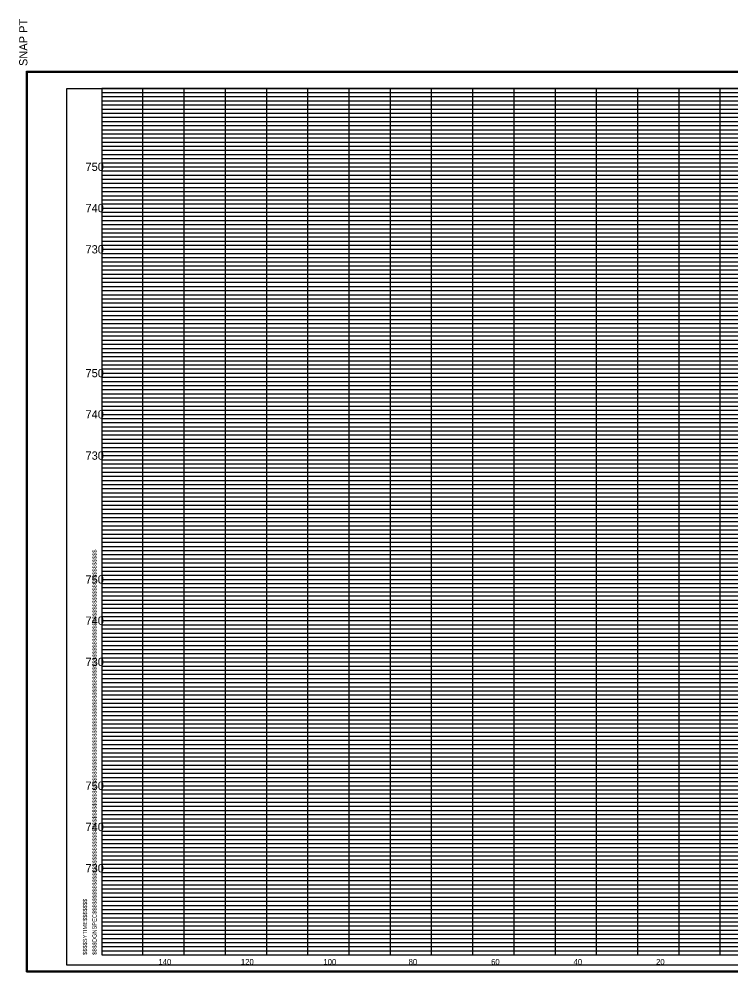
# Model space of a CAD drawing. Extents: x -200 to 1704, y -325 to 2307.
# Drawn here: x 1359.9 to 1532.6, y 995.9 to 1226.8 of the extents above; entities that cross this region are included whole.
import ezdxf

# ---------------------------------------------------------------- set-up
doc = ezdxf.new("R2010")
doc.units = 0
for name, color, linetype in [('DESIGN - SHEET - Corner Text', 7, 'Continuous'), ('DESIGN - SHEET - Light Grid', 7, 'Continuous'), ('DESIGN - SHEET - Linework', 7, 'Continuous'), ('DESIGN - SHEET - Plot Shape', 7, 'Continuous'), ('DESIGN - TYPICAL - Text', 7, 'Continuous')]:
    doc.layers.add(name, color=color, linetype=linetype)

msp = doc.modelspace()

# ---------------------------------------------------------------- linework, layer by layer
at = {"layer": 'DESIGN - SHEET - Light Grid'}
for p, q in [((1380, 1209), (1460, 1209)), ((1380, 1208), (1460, 1208)), ((1460, 1209), (1540, 1209)), ((1460, 1208), (1540, 1208)), ((1380, 1207), (1460, 1207)), ((1380, 1206), (1460, 1206)), ((1460, 1207), (1540, 1207)), ((1460, 1206), (1540, 1206)), ((1380, 1205), (1460, 1205)), ((1380, 1204), (1460, 1204)), ((1460, 1205), (1540, 1205)), ((1460, 1204), (1540, 1204)), ((1380, 1203), (1460, 1203)), ((1380, 1202), (1460, 1202)), ((1380, 1201), (1460, 1201)), ((1460, 1203), (1540, 1203)), ((1460, 1202), (1540, 1202)), ((1460, 1201), (1540, 1201)), ((1380, 1199), (1460, 1199)), ((1460, 1199), (1540, 1199)), ((1380, 1198), (1460, 1198)), ((1380, 1197), (1460, 1197)), ((1460, 1198), (1540, 1198)), ((1460, 1197), (1540, 1197)), ((1380, 1196), (1460, 1196)), ((1380, 1195), (1460, 1195)), ((1460, 1196), (1540, 1196)), ((1460, 1195), (1540, 1195)), ((1380, 1194), (1460, 1194)), ((1380, 1193), (1460, 1193)), ((1380, 1192), (1460, 1192)), ((1460, 1194), (1540, 1194)), ((1460, 1193), (1540, 1193)), ((1460, 1192), (1540, 1192)), ((1380, 1191), (1460, 1191)), ((1460, 1191), (1540, 1191)), ((1380, 1189), (1460, 1189)), ((1380, 1188), (1460, 1188)), ((1460, 1189), (1540, 1189)), ((1460, 1188), (1540, 1188)), ((1380, 1187), (1460, 1187)), ((1380, 1186), (1460, 1186)), ((1380, 1185), (1460, 1185)), ((1460, 1187), (1540, 1187)), ((1460, 1186), (1540, 1186)), ((1460, 1185), (1540, 1185)), ((1380, 1184), (1460, 1184)), ((1380, 1183), (1460, 1183)), ((1460, 1184), (1540, 1184)), ((1460, 1183), (1540, 1183)), ((1380, 1182), (1460, 1182)), ((1380, 1181), (1460, 1181)), ((1460, 1182), (1540, 1182)), ((1460, 1181), (1540, 1181)), ((1380, 1179), (1460, 1179)), ((1380, 1178), (1460, 1178)), ((1460, 1179), (1540, 1179)), ((1460, 1178), (1540, 1178)), ((1380, 1177), (1460, 1177)), ((1380, 1176), (1460, 1176)), ((1460, 1177), (1540, 1177)), ((1460, 1176), (1540, 1176)), ((1380, 1175), (1460, 1175)), ((1380, 1174), (1460, 1174)), ((1460, 1175), (1540, 1175)), ((1460, 1174), (1540, 1174)), ((1380, 1173), (1460, 1173)), ((1380, 1172), (1460, 1172)), ((1380, 1171), (1460, 1171)), ((1460, 1173), (1540, 1173)), ((1460, 1172), (1540, 1172)), ((1460, 1171), (1540, 1171)), ((1380, 1169), (1460, 1169)), ((1460, 1169), (1540, 1169)), ((1380, 1168), (1460, 1168)), ((1380, 1167), (1460, 1167)), ((1460, 1168), (1540, 1168)), ((1460, 1167), (1540, 1167)), ((1380, 1166), (1460, 1166)), ((1380, 1165), (1460, 1165)), ((1380, 1164), (1460, 1164)), ((1460, 1166), (1540, 1166)), ((1460, 1165), (1540, 1165)), ((1460, 1164), (1540, 1164)), ((1380, 1163), (1460, 1163)), ((1380, 1162), (1460, 1162)), ((1460, 1163), (1540, 1163)), ((1460, 1162), (1540, 1162)), ((1380, 1161), (1460, 1161)), ((1460, 1161), (1540, 1161)), ((1380, 1159), (1460, 1159)), ((1380, 1158), (1460, 1158)), ((1460, 1159), (1540, 1159)), ((1460, 1158), (1540, 1158)), ((1380, 1157), (1460, 1157)), ((1380, 1156), (1460, 1156)), ((1380, 1155), (1460, 1155)), ((1460, 1157), (1540, 1157)), ((1460, 1156), (1540, 1156)), ((1460, 1155), (1540, 1155)), ((1380, 1154), (1460, 1154)), ((1380, 1153), (1460, 1153)), ((1460, 1154), (1540, 1154)), ((1460, 1153), (1540, 1153)), ((1380, 1152), (1460, 1152)), ((1380, 1151), (1460, 1151)), ((1460, 1152), (1540, 1152)), ((1460, 1151), (1540, 1151)), ((1380, 1149), (1460, 1149)), ((1380, 1148), (1460, 1148)), ((1460, 1149), (1540, 1149)), ((1460, 1148), (1540, 1148)), ((1380, 1147), (1460, 1147)), ((1380, 1146), (1460, 1146)), ((1460, 1147), (1540, 1147)), ((1460, 1146), (1540, 1146)), ((1380, 1145), (1460, 1145)), ((1380, 1144), (1460, 1144)), ((1460, 1145), (1540, 1145)), ((1460, 1144), (1540, 1144)), ((1380, 1143), (1460, 1143)), ((1380, 1142), (1460, 1142)), ((1380, 1141), (1460, 1141)), ((1460, 1143), (1540, 1143)), ((1460, 1142), (1540, 1142)), ((1460, 1141), (1540, 1141)), ((1380, 1139), (1460, 1139)), ((1460, 1139), (1540, 1139)), ((1380, 1138), (1460, 1138)), ((1380, 1137), (1460, 1137)), ((1460, 1138), (1540, 1138)), ((1460, 1137), (1540, 1137)), ((1380, 1136), (1460, 1136)), ((1380, 1135), (1460, 1135)), ((1380, 1134), (1460, 1134)), ((1460, 1136), (1540, 1136)), ((1460, 1135), (1540, 1135)), ((1460, 1134), (1540, 1134)), ((1380, 1133), (1460, 1133)), ((1380, 1132), (1460, 1132)), ((1460, 1133), (1540, 1133)), ((1460, 1132), (1540, 1132)), ((1380, 1131), (1460, 1131)), ((1460, 1131), (1540, 1131)), ((1380, 1129), (1460, 1129)), ((1380, 1128), (1460, 1128)), ((1460, 1129), (1540, 1129)), ((1460, 1128), (1540, 1128)), ((1380, 1127), (1460, 1127)), ((1380, 1126), (1460, 1126)), ((1380, 1125), (1460, 1125)), ((1460, 1127), (1540, 1127)), ((1460, 1126), (1540, 1126)), ((1460, 1125), (1540, 1125)), ((1380, 1124), (1460, 1124)), ((1380, 1123), (1460, 1123)), ((1460, 1124), (1540, 1124)), ((1460, 1123), (1540, 1123)), ((1380, 1122), (1460, 1122)), ((1380, 1121), (1460, 1121)), ((1460, 1122), (1540, 1122)), ((1460, 1121), (1540, 1121)), ((1380, 1119), (1460, 1119)), ((1380, 1118), (1460, 1118)), ((1460, 1119), (1540, 1119)), ((1460, 1118), (1540, 1118)), ((1380, 1117), (1460, 1117)), ((1380, 1116), (1460, 1116)), ((1460, 1117), (1540, 1117)), ((1460, 1116), (1540, 1116)), ((1380, 1115), (1460, 1115)), ((1380, 1114), (1460, 1114)), ((1460, 1115), (1540, 1115)), ((1460, 1114), (1540, 1114)), ((1380, 1113), (1460, 1113)), ((1380, 1112), (1460, 1112)), ((1380, 1111), (1460, 1111)), ((1460, 1113), (1540, 1113)), ((1460, 1112), (1540, 1112)), ((1460, 1111), (1540, 1111)), ((1380, 1109), (1460, 1109)), ((1460, 1109), (1540, 1109)), ((1380, 1108), (1460, 1108)), ((1380, 1107), (1460, 1107)), ((1460, 1108), (1540, 1108)), ((1460, 1107), (1540, 1107)), ((1380, 1106), (1460, 1106)), ((1380, 1105), (1460, 1105)), ((1380, 1104), (1460, 1104)), ((1460, 1106), (1540, 1106)), ((1460, 1105), (1540, 1105)), ((1460, 1104), (1540, 1104)), ((1380, 1103), (1460, 1103)), ((1380, 1102), (1460, 1102)), ((1460, 1103), (1540, 1103)), ((1460, 1102), (1540, 1102)), ((1380, 1101), (1460, 1101)), ((1460, 1101), (1540, 1101)), ((1380, 1099), (1460, 1099)), ((1380, 1098), (1460, 1098)), ((1460, 1099), (1540, 1099)), ((1460, 1098), (1540, 1098)), ((1380, 1097), (1460, 1097)), ((1380, 1096), (1460, 1096)), ((1380, 1095), (1460, 1095)), ((1460, 1097), (1540, 1097)), ((1460, 1096), (1540, 1096)), ((1460, 1095), (1540, 1095)), ((1380, 1094), (1460, 1094)), ((1380, 1093), (1460, 1093)), ((1460, 1094), (1540, 1094)), ((1460, 1093), (1540, 1093)), ((1380, 1092), (1460, 1092)), ((1380, 1091), (1460, 1091)), ((1460, 1092), (1540, 1092)), ((1460, 1091), (1540, 1091)), ((1380, 1089), (1460, 1089)), ((1380, 1088), (1460, 1088)), ((1460, 1089), (1540, 1089)), ((1460, 1088), (1540, 1088)), ((1380, 1087), (1460, 1087)), ((1380, 1086), (1460, 1086)), ((1460, 1087), (1540, 1087)), ((1460, 1086), (1540, 1086)), ((1380, 1085), (1460, 1085)), ((1380, 1084), (1460, 1084)), ((1460, 1085), (1540, 1085)), ((1460, 1084), (1540, 1084)), ((1380, 1083), (1460, 1083)), ((1380, 1082), (1460, 1082)), ((1380, 1081), (1460, 1081)), ((1460, 1083), (1540, 1083)), ((1460, 1082), (1540, 1082)), ((1460, 1081), (1540, 1081)), ((1380, 1079), (1460, 1079)), ((1460, 1079), (1540, 1079)), ((1380, 1078), (1460, 1078)), ((1380, 1077), (1460, 1077)), ((1460, 1078), (1540, 1078)), ((1460, 1077), (1540, 1077)), ((1380, 1076), (1460, 1076)), ((1380, 1075), (1460, 1075)), ((1380, 1074), (1460, 1074)), ((1460, 1076), (1540, 1076)), ((1460, 1075), (1540, 1075)), ((1460, 1074), (1540, 1074)), ((1380, 1073), (1460, 1073)), ((1380, 1072), (1460, 1072)), ((1460, 1073), (1540, 1073)), ((1460, 1072), (1540, 1072)), ((1380, 1071), (1460, 1071)), ((1460, 1071), (1540, 1071)), ((1380, 1069), (1460, 1069)), ((1380, 1068), (1460, 1068)), ((1380, 1067), (1460, 1067)), ((1460, 1069), (1540, 1069)), ((1460, 1068), (1540, 1068)), ((1460, 1067), (1540, 1067)), ((1380, 1066), (1460, 1066)), ((1380, 1065), (1460, 1065)), ((1460, 1066), (1540, 1066)), ((1460, 1065), (1540, 1065)), ((1380, 1064), (1460, 1064)), ((1380, 1063), (1460, 1063)), ((1460, 1064), (1540, 1064)), ((1460, 1063), (1540, 1063)), ((1380, 1062), (1460, 1062)), ((1380, 1061), (1460, 1061)), ((1460, 1062), (1540, 1062)), ((1460, 1061), (1540, 1061)), ((1380, 1059), (1460, 1059)), ((1380, 1058), (1460, 1058)), ((1460, 1059), (1540, 1059)), ((1460, 1058), (1540, 1058)), ((1380, 1057), (1460, 1057)), ((1380, 1056), (1460, 1056)), ((1460, 1057), (1540, 1057)), ((1460, 1056), (1540, 1056)), ((1380, 1055), (1460, 1055)), ((1380, 1054), (1460, 1054)), ((1460, 1055), (1540, 1055)), ((1460, 1054), (1540, 1054)), ((1380, 1053), (1460, 1053)), ((1380, 1052), (1460, 1052)), ((1380, 1051), (1460, 1051)), ((1460, 1053), (1540, 1053)), ((1460, 1052), (1540, 1052)), ((1460, 1051), (1540, 1051)), ((1380, 1049), (1460, 1049)), ((1460, 1049), (1540, 1049)), ((1380, 1048), (1460, 1048)), ((1380, 1047), (1460, 1047)), ((1460, 1048), (1540, 1048)), ((1460, 1047), (1540, 1047)), ((1380, 1046), (1460, 1046)), ((1380, 1045), (1460, 1045)), ((1380, 1044), (1460, 1044)), ((1460, 1046), (1540, 1046)), ((1460, 1045), (1540, 1045)), ((1460, 1044), (1540, 1044)), ((1380, 1043), (1460, 1043)), ((1380, 1042), (1460, 1042)), ((1460, 1043), (1540, 1043)), ((1460, 1042), (1540, 1042)), ((1380, 1041), (1460, 1041)), ((1460, 1041), (1540, 1041)), ((1380, 1039), (1460, 1039)), ((1380, 1038), (1460, 1038)), ((1380, 1037), (1460, 1037)), ((1460, 1039), (1540, 1039)), ((1460, 1038), (1540, 1038)), ((1460, 1037), (1540, 1037)), ((1380, 1036), (1460, 1036)), ((1380, 1035), (1460, 1035)), ((1460, 1036), (1540, 1036)), ((1460, 1035), (1540, 1035)), ((1380, 1034), (1460, 1034)), ((1380, 1033), (1460, 1033)), ((1460, 1034), (1540, 1034)), ((1460, 1033), (1540, 1033)), ((1380, 1032), (1460, 1032)), ((1380, 1031), (1460, 1031)), ((1460, 1032), (1540, 1032)), ((1460, 1031), (1540, 1031)), ((1380, 1029), (1460, 1029)), ((1380, 1028), (1460, 1028)), ((1460, 1029), (1540, 1029)), ((1460, 1028), (1540, 1028)), ((1380, 1027), (1460, 1027)), ((1380, 1026), (1460, 1026)), ((1460, 1027), (1540, 1027)), ((1460, 1026), (1540, 1026)), ((1380, 1025), (1460, 1025)), ((1380, 1024), (1460, 1024)), ((1460, 1025), (1540, 1025)), ((1460, 1024), (1540, 1024)), ((1380, 1023), (1460, 1023)), ((1380, 1022), (1460, 1022)), ((1380, 1021), (1460, 1021)), ((1460, 1023), (1540, 1023)), ((1460, 1022), (1540, 1022)), ((1460, 1021), (1540, 1021)), ((1380, 1019), (1460, 1019)), ((1460, 1019), (1540, 1019)), ((1380, 1018), (1460, 1018)), ((1380, 1017), (1460, 1017)), ((1460, 1018), (1540, 1018)), ((1460, 1017), (1540, 1017)), ((1380, 1016), (1460, 1016)), ((1380, 1015), (1460, 1015)), ((1380, 1014), (1460, 1014)), ((1460, 1016), (1540, 1016)), ((1460, 1015), (1540, 1015)), ((1460, 1014), (1540, 1014)), ((1380, 1013), (1460, 1013)), ((1380, 1012), (1460, 1012)), ((1460, 1013), (1540, 1013)), ((1460, 1012), (1540, 1012)), ((1380, 1011), (1460, 1011)), ((1460, 1011), (1540, 1011)), ((1380, 1009), (1460, 1009)), ((1380, 1008), (1460, 1008)), ((1380, 1007), (1460, 1007)), ((1460, 1009), (1540, 1009)), ((1460, 1008), (1540, 1008)), ((1460, 1007), (1540, 1007)), ((1380, 1006), (1460, 1006)), ((1380, 1005), (1460, 1005)), ((1460, 1006), (1540, 1006)), ((1460, 1005), (1540, 1005)), ((1380, 1004), (1460, 1004)), ((1380, 1003), (1460, 1003)), ((1460, 1004), (1540, 1004)), ((1460, 1003), (1540, 1003)), ((1380, 1002), (1460, 1002)), ((1380, 1001), (1460, 1001)), ((1460, 1002), (1540, 1002)), ((1460, 1001), (1540, 1001))]:
    msp.add_line(p, q, dxfattribs=at)
at = {"layer": 'DESIGN - SHEET - Linework'}
for p, q in [((1361.77, 995.86), (1361.77, 1214.14)), ((1361.77, 1214.14), (1702.17, 1214.14)), ((1390, 1000), (1390, 1210)), ((1400, 1000), (1400, 1210)), ((1410, 1000), (1410, 1210)), ((1420, 1000), (1420, 1210)), ((1430, 1000), (1430, 1210)), ((1440, 1000), (1440, 1210)), ((1450, 1000), (1450, 1210)), ((1460, 1000), (1460, 1210)), ((1470, 1000), (1470, 1210)), ((1480, 1000), (1480, 1210)), ((1490, 1000), (1490, 1210)), ((1500, 1000), (1500, 1210)), ((1510, 1000), (1510, 1210)), ((1520, 1000), (1520, 1210)), ((1530, 1000), (1530, 1210)), ((1380, 1200), (1660, 1200)), ((1380, 1190), (1700, 1190)), ((1380, 1180), (1700, 1180)), ((1380, 1170), (1700, 1170)), ((1380, 1160), (1700, 1160)), ((1380, 1150), (1700, 1150)), ((1380, 1140), (1700, 1140)), ((1380, 1130), (1700, 1130)), ((1380, 1120), (1700, 1120)), ((1380, 1110), (1700, 1110)), ((1380, 1100), (1700, 1100)), ((1380, 1090), (1700, 1090)), ((1380, 1080), (1700, 1080)), ((1380, 1070), (1700, 1070)), ((1380, 1060), (1700, 1060)), ((1380, 1050), (1700, 1050)), ((1380, 1040), (1700, 1040)), ((1380, 1030), (1700, 1030)), ((1380, 1020), (1700, 1020)), ((1380, 1010), (1700, 1010)), ((1361.77, 995.86), (1702.17, 995.86))]:
    msp.add_line(p, q, dxfattribs=at)
msp.add_lwpolyline([(1380, 1210), (1380, 1000), (1700, 1000), (1700, 1210), (1380, 1210)], dxfattribs=at)
at = {"layer": 'DESIGN - SHEET - Plot Shape'}
for points in [[(1361.97, 1213.94), (1701.97, 1213.94), (1701.97, 996.06), (1361.97, 996.06)], [(1371.5, 1210), (1700, 1210), (1700, 997.5), (1371.5, 997.5)]]:
    msp.add_lwpolyline(points, close=True, dxfattribs=at)

# ---------------------------------------------------------------- texts
at = {"layer": 'DESIGN - SHEET - Corner Text'}
for s, height, p in [('  SNAP PT', 2, (1361.97, 1213.94)), ('$$$$DGNSPEC$$$$$$$$$$$$$$$$$$$$$$$$$$$$$$$$$$$$$$$$$$$$$$$$$$$$$$$$$$$$$$$$$$$$$$$$$$$$$$$$$$$$$$$$$$$$$$$$$$$$$$$$$$$$$$$$$$$', 1.00002, (1378.74, 1000)), ('$$$$SYTIME$$$$$$$', 1, (1376.42, 1000))]:
    msp.add_text(s, height=height, rotation=90, dxfattribs=at).set_placement(p)
at = {"layer": 'DESIGN - TYPICAL - Text'}
for s, height, p in [('     750     ', 2, (1372.34, 1190)), ('     740     ', 2, (1372.34, 1180)), ('     730     ', 2, (1372.34, 1170)), ('     750     ', 2, (1372.34, 1140)), ('     740     ', 2, (1372.34, 1130)), ('     730     ', 2, (1372.34, 1120)), ('     750     ', 2, (1372.34, 1090)), ('     740     ', 2, (1372.34, 1080)), ('     730     ', 2, (1372.34, 1070)), ('     750     ', 2, (1372.34, 1040)), ('     740     ', 2, (1372.34, 1030)), ('     730     ', 2, (1372.34, 1020)), ('     140     ', 1.4, (1391.14, 997.6)), ('     120     ', 1.4, (1411.14, 997.6)), ('     100     ', 1.4, (1431.14, 997.6)), ('     80     ', 1.4, (1451.82, 997.6)), ('     60     ', 1.4, (1471.82, 997.6)), ('     40     ', 1.4, (1491.82, 997.6)), ('     20     ', 1.4, (1511.82, 997.6))]:
    msp.add_text(s, height=height, dxfattribs=at).set_placement(p)

doc.saveas('drawing.dxf')
